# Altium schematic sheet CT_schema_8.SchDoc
size 277 x 170 mm
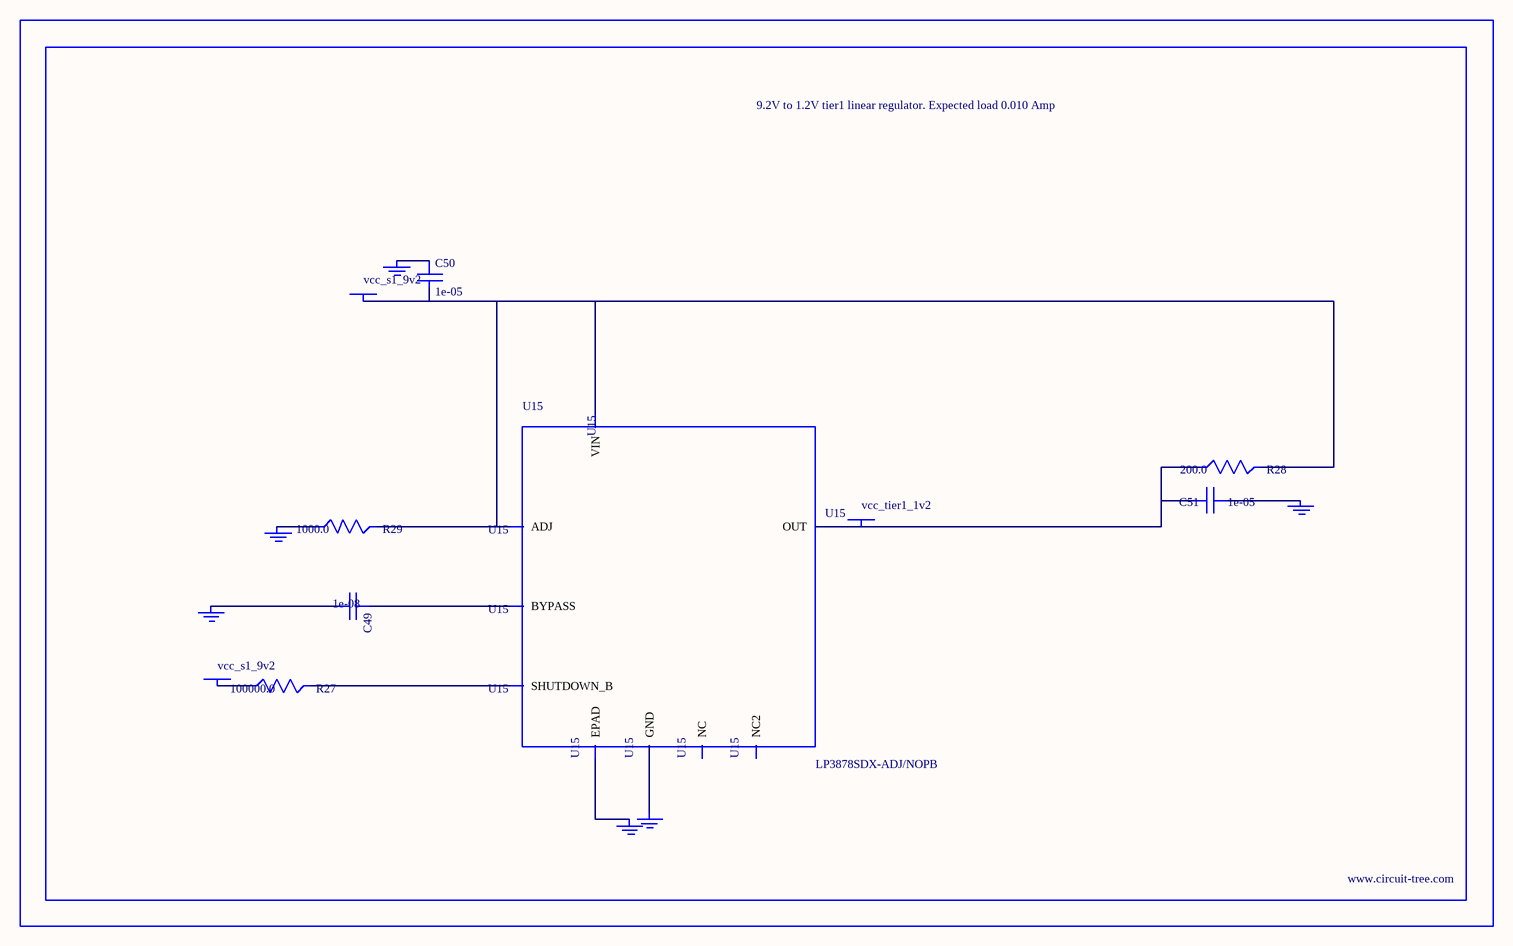
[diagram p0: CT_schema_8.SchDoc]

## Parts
BORDER7  (no value)
C49  1e-08  [C0402]
C50  1e-05  [C1206]
C51  1e-05  [C0805]
GND_INSTANCE_7_0  (no value)
GND_INSTANCE_7_1  (no value)
GND_INSTANCE_7_2  (no value)
GND_INSTANCE_7_3  (no value)
GND_INSTANCE_7_4  (no value)
GND_INSTANCE_7_5  (no value)
POWER_INSTANCE_7_0  vcc_s1_9v2
POWER_INSTANCE_7_1  vcc_s1_9v2
POWER_INSTANCE_7_2  vcc_tier1_1v2
R27  100000.0  [R0603]
R28  200.0  [R0603]
R29  1000.0  [R0603]
U15  LP3878SDX-ADJ/NOPB  [WSON-8]

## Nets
NetC49_1: C49.1 U15.1(BYPASS)
NetC49_2: C49.2 GND_INSTANCE_7_0.0(GND)
NetC50_1: C50.1 GND_INSTANCE_7_1.0(GND)
NetC50_2: C50.2 POWER_INSTANCE_7_0.0(PWR) R28.2 R29.2 U15.4(VIN) U15.6(ADJ)
NetC51_1: C51.1 GND_INSTANCE_7_2.0(GND)
NetC51_2: C51.2 POWER_INSTANCE_7_2.0(PWR) R28.1 U15.5(OUT)
NetGND_INSTANCE_7_3_0: GND_INSTANCE_7_3.0(GND) R29.1
NetGND_INSTANCE_7_4_0: GND_INSTANCE_7_4.0(GND) U15.PAD(EPAD)
NetGND_INSTANCE_7_5_0: GND_INSTANCE_7_5.0(GND) U15.3(GND)
NetPOWER_INSTANCE_7_1_0: POWER_INSTANCE_7_1.0(PWR) R27.1
NetR27_2: R27.2 U15.8(SHUTDOWN_B)

Not connected (* = marked no-connect by the designer): U15 2(NC) 7(NC2)

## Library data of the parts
BORDER7 = BORDER_PAGE7
C49 = C0402C103K3RAC
C50 = C1206C106K3RACTU
C51 = GRM219R60J106ME19D
GND_INSTANCE_7_0-GND_INSTANCE_7_5 = GND
POWER_INSTANCE_7_0-POWER_INSTANCE_7_2 = PWR
R27 = RC0603JR-07100KL
R28 = RC0603JR-07200RL
R29 = RC0603JR-071KL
